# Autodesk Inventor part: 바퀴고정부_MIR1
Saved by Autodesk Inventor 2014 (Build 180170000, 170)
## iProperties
Created: 2015-05
Part Number: 바퀴고정부_MIR1
Material: 일반
Vendor: CBT Solutions
Document SubType Name: 모델링
Designer: Administrator
Appearance: 기본값
Company: 한국ATC센터
Author: KYOUNG IL JANG
Comments: 파생
d0: 1.000 ul
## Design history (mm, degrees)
derived "바퀴고정부.ipt" dims count "d0" = 1
feature "솔리드1::바퀴고정부.ipt" dims count "d0" = 1
tag "피쳐 태그1"
node "솔리드1"
